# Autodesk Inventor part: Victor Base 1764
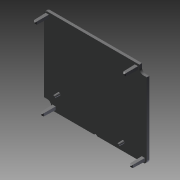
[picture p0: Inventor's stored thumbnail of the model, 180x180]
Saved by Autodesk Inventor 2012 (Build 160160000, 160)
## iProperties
Shininess: 64.0
Length Units: 11272
Angle Units: 11279
Time Units: 11290
Mass Units: 11286
Length Display Precision: 3
Angle Display Precision: 2
Compacted: True
Part Number: Victor Base 1764
Document SubType Name: Modeling
Created: 2007-01
Designer: uidk0133
Density: 1 g/cm^3
Material: Default
Density: 0.0
Volumn: 0.0
Area: 0.0
PropertySet Name: Model Information
Control State: 0
Master: False
Checked Out: False
Translation Standard: STEP AP203
File Name: V883-003 RevH.stp
Preprocessor: THINKDESIGN
Postprocessor: Build: Release: 6 RTM Build: 90b - Date: Tue 09/24/2002
Sent Units: INCHES
Uncertainty: 0.0
Author: uidk0133
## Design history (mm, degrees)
feature "Base1"
body "Solid1"
